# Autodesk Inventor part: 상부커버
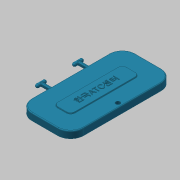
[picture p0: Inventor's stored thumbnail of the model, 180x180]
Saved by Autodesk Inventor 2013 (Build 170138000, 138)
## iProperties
Created: 2016-02
Part Number: 상부커버
Material: ABS 플라스틱
Document SubType Name: Modeling
Designer: mduedu
Density: 1.06 g/cm^3
Mass: 61.4476 g
Surface Area: 174.433 cm^2
Volume: 57.9694 cm^3
Author: mduedu
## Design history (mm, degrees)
sketch "스케치1"
  geometry: L1 (30, 60)-(-30, 60); L2 (-30, 60)-(-30, -60); L3 (-30, -60)-(30, -60); L4 (30, -60)-(30, 60); L5 (30, 60)-(-30, -60); L6 (-30, 60)-(30, -60); 1 further point
  constraints: 12 end point, 2 midpoint, 2 parallel, 1 horizontal, 1 perpendicular
  dimensions: "d0" = 60 distance of L2.end L3.end; "d2" = 120 distance of L1.end L2.end
extrude "돌출1" new body sketch "스케치1" distance "d3" = 8; taper "d4" = 0 deg
fillet "모깎기1" dims "d5" = 15
node "작업 평면1"
sketch "스케치7"
  geometry: L1 (-39, 4)-(129, 4) reference; L2 (65, 2)-(68, 2); L3 (68, 2)-(68, 6); L4 (68, 6)-(65, 6); L5 (65, 6)-(65, 2); L6 (65, 2)-(68, 6); L7 (68, 2)-(65, 6); 2 further points
  constraints: 12 end point, 2 midpoint, 2 parallel, 1 horizontal, 1 perpendicular, 1 point on line
  dimensions: "d33" = 4 distance of L2.end L3.end; "d35" = 3 distance of L3.end L4.end; "d36" = 20 distance from line of L5 point (45, 0)
extrude "돌출3" join sketch "스케치7" distance "d37" = 15; taper "d38" = 0 deg
fillet "모깎기6" dims "d39" = 2
node "작업 평면3"
sketch "스케치8"
  geometry: A1 r 2 centre (-13, 2) between (-13, 4) and (-13, 0) reference; 2 further points
  constraints: 1 coincident, 1 vertical alignment, 2 other
extrude "돌출4" join sketch "스케치8" stored distance "d40" = 12; taper "d41" = 0 deg
fillet "모깎기7" dims "d42" = 2
fillet "모깎기8" dims "d43" = 1
fillet "모깎기9" dims "d44" = 1
sketch "스케치2"
  geometry: L1 (30, 45)-(30, -45) reference; L2 (15, -60)-(-15, -60) reference; L3 (-30, -45)-(-30, 45) reference; L4 (-15, 60)-(15, 60) reference; L5 (25, 45)-(25, -45); L6 (15, -55)-(-15, -55); L7 (-25, -45)-(-25, 45); L8 (-15, 55)-(15, 55); A1 r 15 centre (15, 45) between (30, 45) and (15, 60) reference; A2 r 15 centre (15, -45) between (15, -60) and (30, -45) reference; A3 r 15 centre (-15, -45) between (-30, -45) and (-15, -60) reference; A4 r 15 centre (-15, 45) between (-15, 60) and (-30, 45) reference; A5 r 10 centre (15, 45) between (25, 45) and (15, 55); A6 r 10 centre (15, -45) between (15, -55) and (25, -45); A7 r 10 centre (-15, -45) between (-25, -45) and (-15, -55); A8 r 10 centre (-15, 45) between (-15, 55) and (-25, 45); 4 further points
  constraints: 8 end point, 8 point on circle, 4 centre point, 4 midpoint, 7 other
  dimensions: "d8" = 5 distance between parallel lines of L7 L3
hole "구멍1" sketch "스케치2" at (25, 0) diameter "d9" = 5; stored, may be unused: countersink angle "d13" = 90 deg, drill point angle "d15" = 118 deg; dims "d10" = 6, "d11" = 4, "d12" = 2, "d14" = 8
sketch "스케치3"
  geometry: L1 (10, -40)-(-10, -40); L2 (-10, -40)-(-10, 40); L3 (-10, 40)-(10, 40); L4 (10, 40)-(10, -40); L5 (10, -40)-(-10, 40); L6 (-10, -40)-(10, 40); 1 further point
  constraints: 12 end point, 2 midpoint, 2 parallel, 1 horizontal, 1 perpendicular
  dimensions: "d16" = 80 distance of L1.end L2.end; "d18" = 20 distance of L2.end L3.end
extrude "돌출2" join sketch "스케치3" distance "d19" = 1; taper "d20" = 0 deg
fillet "모깎기2" dims "d21" = 5
fillet "모깎기3" dims "d22" = 0.3
sketch "스케치4"
  geometry: 2 further points
  constraints: 1 coincident, 1 other
feature "엠보싱1" sketch "스케치4" dims "d8" = 5, "d24" = 0.5, "d25" = 0
fillet "모깎기10" dims "d45" = 1
node "솔리드1"
mirror "대칭1"
node "절단 모서리 투영1"
